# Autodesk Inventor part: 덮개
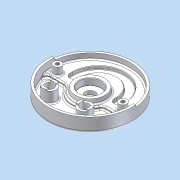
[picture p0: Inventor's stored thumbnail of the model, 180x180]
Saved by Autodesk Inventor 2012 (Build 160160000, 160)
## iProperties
Company: 한국ATC센터
Created: 2015-04
Part Number: 덮개
Document SubType Name: Modeling
Designer: KYOUNG IL JANG
Density: 2.71 g/cm^3
Material: 알루미늄-6061
Author: KYOUNG IL JANG
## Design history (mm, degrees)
sketch "스케치1"
  geometry: L1 (-59, -19)-(-59, 19); L2 (59, 19)-(59, -19); L3 (-41, 19)-(-41, -19); L4 (41, -19)-(41, 19); L5 (59, 5)-(41, 5); L6 (-41, 5)-(-59, 5); C1 r 90 at (0, 0); C2 r 95 at (0, 0); A1 r 59 centre (0, 19) between (59, 19) and (-59, 19); A2 r 59 centre (0, -19) between (-59, -19) and (59, -19); A3 r 41 centre (0, -19) between (-41, -19) and (41, -19); A4 r 41 centre (0, 19) between (41, 19) and (-41, 19); 2 further points
  constraints: 12 end point, 8 point on circle, 6 centre point, 4 point on line, 4 tangent, 2 parallel, 2 perpendicular, 1 coincident, 1 collinear, 1 horizontal alignment, 1 midpoint, 1 vertical, 1 vertical alignment, 3 other
  dimensions: "d2" = 180 diameter of C1; "d3" = 156 dimension on A2 A1; "d4" = 118 distance between parallel lines of L2 L1; "d5" = 18 distance between parallel lines of L2 L4; "d8" = 190 diameter of C2; "d121" = 5 distance from line of L5 point (0, 0)
extrude "돌출1" new body sketch "스케치1" distance "d6" = 14; taper "d7" = 0 deg
extrude "돌출2" join sketch "스케치1" distance "d9" = 13; taper "d10" = 0 deg
extrude "돌출3" cut sketch "스케치1" distance "d11" = 7; taper "d12" = 0 deg
sketch "스케치2"
  geometry: C1 r 11.5 at (0, 0); 1 further point
  constraints: 1 centre point, 1 coincident
  dimensions: "d13" = 23 diameter of C1
extrude "돌출4" cut sketch "스케치2" stored distance "d14" = 7; taper "d15" = 0 deg
fillet "모깎기1"
fillet "모깎기2"
sketch "스케치3"
  geometry: L1 (-89.658, 7.844)-(-94.638, 8.28); L2 (89.658, 7.844)-(94.638, 8.28); L3 (0, 0)-(0, -90); A1 r 95 centre (0, 0) between (-94.638, 8.28) and (94.638, 8.28) reference; A2 r 90 centre (0, 0) between (-89.658, 7.844) and (89.658, 7.844) reference; 1 further point
  constraints: 6 end point, 5 point on circle, 1 point on line, 1 vertical, 1 other
  dimensions: "d16" = 190 deg dimension on L2 L1
extrude "돌출5" join sketch "스케치3" distance "d17" = 5; taper "d18" = 0 deg
hole "구멍1" diameter "d21" = 50; stored, may be unused: countersink angle "d25" = 90 deg, drill point angle "d27" = 0 deg; dims "d19" = 10, "d20" = 10, "d22" = 6, "d23" = 4, "d24" = 2, "d26" = 5
fillet "모깎기3" dims "d28" = 0.3
fillet "모깎기5" dims "d30" = 3
sketch "스케치4"
  geometry: C1 r 35 at (0, 0); C2 r 25 at (0, 0); 1 further point
  constraints: 2 centre point, 1 coincident
  dimensions: "d32" = 70 diameter of C1 (derived); "d36" = 10 radial gap between concentric circles of C1 C2
extrude "돌출6" join sketch "스케치4" distance "d33" = 10; taper "d34" = 0 deg
feature "면 기울기2" dims angle "d37" = 10 deg
chamfer "모따기1" distance "d39" = 1; stored, may be unused: second distance "d40" = 2, angle "d41" = 45 deg
fillet "모깎기7" dims "d42" = 5
sketch "스케치5"
  geometry: L1 (-40.249, -12)-(-89.196, -12); L2 (40.249, -12)-(89.196, -12); A1 r 90 centre (0, 0) between (-89.196, -12) and (89.196, -12) reference; A2 r 42 centre (0, 0) between (-40.249, -12) and (40.249, -12); 1 further point
  constraints: 4 end point, 4 point on circle, 1 centre point, 1 collinear, 1 horizontal, 1 point on line
  dimensions: "d43" = 48 radial gap between concentric circles of A1 A2; "d44" = 12 distance from line of point (0, 0) L1
extrude "돌출7" cut sketch "스케치5" stored distance "d45" = 10; taper "d46" = 0 deg
fillet "모깎기8" dims "d47" = 10
chamfer "모따기2" distance "d49" = 1; stored, may be unused: second distance "d50" = 2, angle "d51" = 45 deg
sketch "스케치8"
  geometry: C1 r 9 at (74, 0); C2 r 9 at (-74, 0); A1 r 74 centre (0, 0) between (74, 0) and (-74, 0); 1 further point
  constraints: 3 centre point, 2 horizontal alignment, 2 point on circle, 1 coincident, 1 equal radius
  dimensions: "d64" = 18 diameter of C1; "d65" = 148 diameter of A1
extrude "돌출9" join sketch "스케치8" stored distance "d66" = 5; taper "d67" = 0 deg
sketch "스케치11"
  geometry: C1 r 15 at (40, -52); C2 r 15 at (-40, -52); 1 further point
  constraints: 2 centre point, 1 equal radius, 1 horizontal alignment
  dimensions: "d82" = 52 vertical distance of point (0, 0) C1.centre; "d83" = 30 diameter of C1; "d84" = 80 distance of C2.centre C1.centre; "d85" = 40 horizontal distance of point (0, 0) C1.centre (= 0.5 x d84)
extrude "돌출10" join sketch "스케치11" stored distance "d86" = 10; taper "d87" = 0 deg
node "구멍3"
node "구멍5"
hole "구멍6" diameter "d92" = 20; stored, may be unused: countersink angle "d96" = 90 deg, drill point angle "d98" = 118 deg; dims "d90" = 10, "d91" = 10, "d93" = 6, "d94" = 4, "d95" = 2, "d97" = 8
hole "구멍7" diameter "d101" = 20; stored, may be unused: countersink angle "d105" = 90 deg, drill point angle "d107" = 118 deg; dims "d99" = 10, "d100" = 10, "d102" = 6, "d103" = 4, "d104" = 2, "d106" = 8
fillet "모깎기13" dims "d108" = 3
sketch "스케치13"
  geometry: L1 (-20.252, -58)-(-26, -58); L2 (-42, -58)-(-47.748, -58); L3 (-20.252, -46)-(-26, -46); L4 (-42, -46)-(-47.748, -46); L5 (-108, -65.748)-(-108, -60); L6 (-108, -44)-(-108, -38.252); L7 (-120, -44)-(-120, -38.252); L8 (-120, -60)-(-120, -65.748); A1 r 15 centre (-34, -52) between (-20.252, -58) and (-47.748, -58) reference; A2 r 10 centre (-34, -52) between (-26, -58) and (-42, -58) reference; A3 r 15 centre (-114, -52) between (-108, -65.748) and (-108, -38.252) reference; A4 r 10 centre (-114, -52) between (-108, -60) and (-108, -44) reference; 1 further point
  constraints: 16 end point, 16 point on circle, 3 equal length, 3 point on line, 2 collinear, 1 horizontal, 1 perpendicular
  dimensions: "d114" = 12 distance between parallel lines of L4 L2; "d115" = 6 distance from line of A1.centre L2 (= 0.5 x d114); "d116" = 12 distance between parallel lines of L8 L5 (= d114); "d117" = 6 distance from line of A3.centre L5 (= d115)
extrude "돌출12" join sketch "스케치13" distance "d118" = 3; taper "d119" = 0 deg
fillet "모깎기14" dims "d120" = 1
node "솔리드1"
sketch "스케치9"
  geometry: 1 further point
hole "구멍2" sketch "스케치9" diameter "d68" = 8.376; stored, may be unused: countersink angle "d72" = 90 deg, drill point angle "d74" = 120 deg; dims "d69" = 16, "d70" = 4, "d71" = 2, "d73" = 21
sketch "스케치10"
  geometry: 1 further point
hole "구멍4" sketch "스케치10" diameter "d75" = 8.376; stored, may be unused: countersink angle "d79" = 90 deg, drill point angle "d81" = 120 deg; dims "d76" = 16, "d77" = 4, "d78" = 2, "d80" = 21
